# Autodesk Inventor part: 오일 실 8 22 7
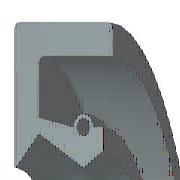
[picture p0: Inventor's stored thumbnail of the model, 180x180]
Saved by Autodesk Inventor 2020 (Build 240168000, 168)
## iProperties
IsCustomPart: 1
Created: 2012-02
Part Number: 오일 실 8 22 7
Material: 고무
Description: 오일-실
Document SubType Name: Modeling
Standard: KS B 2804
Designer: mduedu
Standards Organization: KS
Language: ko-KR
Size Designation: D - 8 22 7
Categories: <MemberInstance><Categories><Category DisplayName="샤프트 부품" InternalName="7f7aeb1f-a693-4053-b835-cee3144e0d98" Mnemonic="SHFT"><Category DisplayName="실링" Intern
Density: 0.93 g/cm^3
Appearance: 고무 - 검은색 - 버전 1.1
Author: mduedu
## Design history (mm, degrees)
revolve "본체" stored, may be unused: angle "d17" = 90 deg
revolve "스프링1" stored, may be unused: angle "d18" = 90 deg
body "Solid1"
sketch "스케치1"
  geometry: L1 (0, 11)-(7, 11); L2 (7, 9.25)-(1.75, 9.25); L3 (1.75, 5.75)-(4.9, 4); L4 (4.9, 4)-(0, 4); L5 (0, 0)-(9.586, 0) reference; L6 (4.9, 4)-(6.3, 4.875); L7 (0, 18)-(0, -3) reference; L8 (-1.941, 0)-(11.507, 0) reference; L9 (4.2, 6.1)-(1.75, 6.59); L10 (1.75, 6.59)-(1.75, 9.25); L11 (0, 11)-(0, 4.088); L12 (4.9, 4)-(0, 4); L13 (1.75, 5.75)-(0.152, 4.028); L14 (7, 11)-(7, 9.25); L15 (5.6, 6.1)-(6.3, 6.1); L16 (6.3, 6.1)-(6.3, 4.875); C1 r 0.455 at (4.9, 6.1); A1 r 0.7 centre (4.9, 6.1) between (5.6, 6.1) and (4.2, 6.1); A2 r 0.088 centre (0.088, 4.088) between (0, 4.088) and (0.152, 4.028); 1 further point
  constraints: 28 end point, 5 horizontal alignment, 5 point on line, 4 point on circle, 4 vertical alignment, 3 centre point, 3 tangent, 2 collinear, 2 horizontal, 2 perpendicular, 1 coincident, 1 parallel
  dimensions: "d0" = 22 diameter of L1 L5 (= SD2); "d1" = 1.75 distance of L1.end L2.start (= SD); "d2" = 0.91 diameter of C1 (= SPDI); "d3" = 1.4 diameter of A1 (= SPDA); "d4" = 8 diameter of L3.end L5 (= NND); "d5" = 11.5 diameter of L3.start L5 (= TKDM); "d7" = 13.18 diameter of L9.end L5 (= TKDM + 0.24 x SWDT); "d8" = 1.75 distance between parallel lines of L11 L10 (= SD); "d9" = 4.9 distance from line of L11 C1.centre (= SPDST); "d10" = 12.2 diameter of C1.centre L5 (= HLDM); "d11" = 0.0875 radius of A2 (= 0.25 x LAB); "d12" = 6.3 distance between parallel lines of L11 L16 (= SDI); "d13" = 9.75 diameter of L6.end L5 (= ABDM); "d14" = 7 distance from line of L11 L1.end (= SWDT)
fillet "모깎기1" dims "d6" = 0.3 (= RR)
other parameters: "SD2" = 22 [user parameter; used in 1 equation term], "SWDT" = 7 [user parameter; used in 2 equation terms], "RR" = 0.3 [user parameter; used in 1 equation term], "SD" = 1.75 [user parameter; used in 2 equation terms], "NND" = 8 [user parameter; used in 1 equation term], "SPDA" = 1.4 [user parameter; used in 1 equation term], "SPDI" = 0.91 [user parameter; used in 1 equation term], "TKDM" = 11.5 [user parameter; used in 2 equation terms], "HLDM" = 12.2 [user parameter; used in 1 equation term], "ABDM" = 9.75 [user parameter; used in 1 equation term], "SDI" = 6.3 [user parameter; used in 1 equation term], "SPDST" = 4.9 [user parameter; used in 1 equation term], "LAB" = 0.35 [user parameter; used in 1 equation term], "d15" = 0, "d16" = 0, "d19" = 0
